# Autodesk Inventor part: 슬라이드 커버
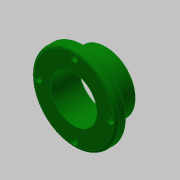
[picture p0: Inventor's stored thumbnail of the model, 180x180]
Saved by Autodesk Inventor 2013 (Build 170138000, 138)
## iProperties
Created: 2015-10
Part Number: 슬라이드 커버
Document SubType Name: Modeling
Designer: mdu
Density: 1 g/cm^3
Material: 알루미늄 6061
Mass: 76.148 g
Surface Area: 229.996 cm^2
Volume: 76.148 cm^3
Author: mdu
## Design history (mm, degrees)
sketch "스케치1"
  geometry: C1 r 46 at (0, -39.25) reference; C2 r 32.5 at (0, -39.25) reference; 1 further point
  node "참조1"
  node "참조2"
extrude "돌출1" new body sketch "스케치1" distance "d0" = 10; taper "d1" = 0 deg
extrude "돌출2" join sketch "스케치1" distance "d2" = 25; taper "d3" = 0 deg
hole "구멍1" diameter "d6" = 50; stored, may be unused: countersink angle "d10" = 90 deg, drill point angle "d12" = 118 deg; dims "d4" = 10, "d5" = 10, "d7" = 6, "d8" = 4, "d9" = 2, "d11" = 8
sketch "스케치2"
  geometry: C1 r 46 at (0, 0) reference; C2 r 1.621 at (0, 39) reference; C3 r 1.621 at (39, 0) reference; C4 r 1.621 at (0, -39) reference; C5 r 1.621 at (-39, 0) reference; C6 r 33.5 at (0, 0) reference; 1 further point
hole "구멍2" sketch "스케치2" at (0, 39) diameter "d13" = 4.5; stored, may be unused: countersink angle "d17" = 90 deg, drill point angle "d19" = 118 deg; dims "d14" = 6, "d15" = 8, "d16" = 4.4, "d18" = 8
fillet "모깎기1" dims "d23" = 3
chamfer "모따기1" distance "d24" = 1; stored, may be unused: second distance "d25" = 2, angle "d26" = 45 deg
sketch "스케치3"
  geometry: C1 r 25 at (0, 0); C2 r 30 at (0, 0); C3 r 26 at (0, 0) reference; 1 further point
  constraints: 2 centre point, 2 coincident
  dimensions: "d27" = 60 diameter of C2
extrude "돌출3" cut sketch "스케치3" distance "d28" = 3; taper "d29" = 0 deg
chamfer "모따기2" distance "d30" = 1; stored, may be unused: second distance "d31" = 2, angle "d32" = 45 deg
node "솔리드1"
pattern_circular "원형 패턴1" dims angle "d21" = 360 deg
node "참조3"
